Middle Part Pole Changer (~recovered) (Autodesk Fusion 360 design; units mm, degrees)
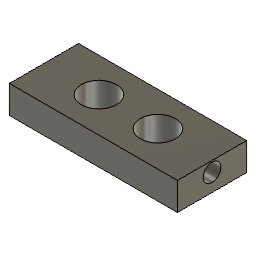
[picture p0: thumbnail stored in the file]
part number: 2026-03-20-14-52-07-281
sketch "Sketch1" plane through (0, 0, 0) normal (0, 1, 0) x axis (1, 0, 0)
  line L1 (71.8058, 0) -> (0, 0)
  line L2 (71.8058, -11.9126) -> (71.8058, 0)
  line L3 (0, -11.9126) -> (71.8058, -11.9126)
  line L4 (0, 0) -> (0, -11.9126)
  point P1 (0, 0)
  point P2 (0, 0)
  point P3 (71.8058, 0)
  point P5 (0, -11.9126)
  horizontal L1
  vertical L2
  horizontal L3
  vertical L4
  coincident P1 P2
  dimension "d1" distance P2 P3 = 71.8058
  dimension "d2" distance P2 P5 = 11.9126
extrude "Extrude1" new body sketch "Sketch1" along normal blind 29.591
hole "Hole2" HoleDepth 7.8486 HoleDiameter 7.5438 TipAngle 118
mirror "Mirror1" mirrorStitchTolerance 0.1016
hole "Hole3" HoleDepth 11.938 HoleDiameter 14.986 TipAngle 118
mirror "Mirror2" mirrorStitchTolerance 0.1016
hole "Hole1" HoleDepth 7.8486 HoleDiameter 7.62 TipAngle 118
